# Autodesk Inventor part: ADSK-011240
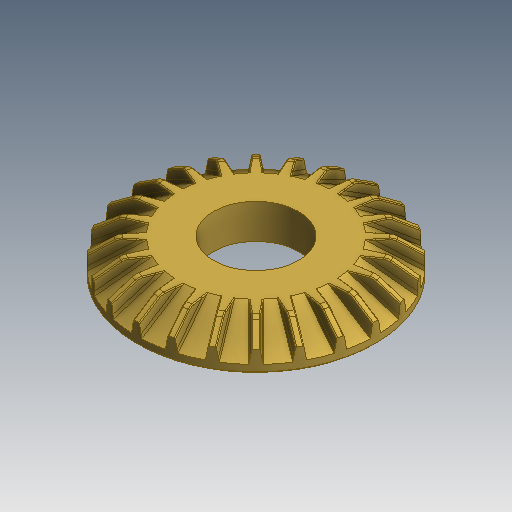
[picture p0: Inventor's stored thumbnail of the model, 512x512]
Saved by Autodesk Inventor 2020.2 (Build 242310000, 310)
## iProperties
Created: 2000-10
Part Number: ADSK-011240
Document SubType Name: Modeling
Designer: wymerj
Material: Générique
Density: 1 g/cm^3
Appearance: Vorgabe
Mass: 96.213 g
Surface Area: 231.242 cm^2
Volume: 96.213 cm^3
Control State: 0
Master: False
Checked Out: False
Shininess: 0.0
Length Units: 11269
Angle Units: 11279
Time Units: 11290
Mass Units: 11283
Length Display Precision: 3
Angle Display Precision: 2
Compacted: True
Dimensions: 15,6x107,2x107,2 mm
Mass: 0,096 kg
VLT_Material: Generic
Density: 0.0
Volumn: 0.0
Area: 0.0
PropertySet Name: Model Information
Author: wymerj
Revision Number: -
Title: ADSK-011240
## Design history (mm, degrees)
derived "ADSK-011239.ipt"
  workplane "Work Plane1"
  workaxis "Work Axis1"
  workaxis "Work Axis2"
node "Extrusion1" dims "d2" = 10, "d3" = 0
node "Solide1"
node "Corps solides"
node "Corps surfaciques"
node "FonctionRepérage2"
sketch "Sketch2"
  geometry: 6 further points; 4 other entities
  constraints: 2 vertical alignment, 1 horizontal alignment, 3 other
sketch "Sketch3"
  geometry: C1 r 52.94 at (0, 0) reference; C2 r 19.05 at (0, 0)
  constraints: 1 centre point, 1 coincident
  dimensions: "d1" = 38.1 diameter of C2
feature "DerivedBody::ADSK-011239.ipt"
other parameters: "d0" = 35
